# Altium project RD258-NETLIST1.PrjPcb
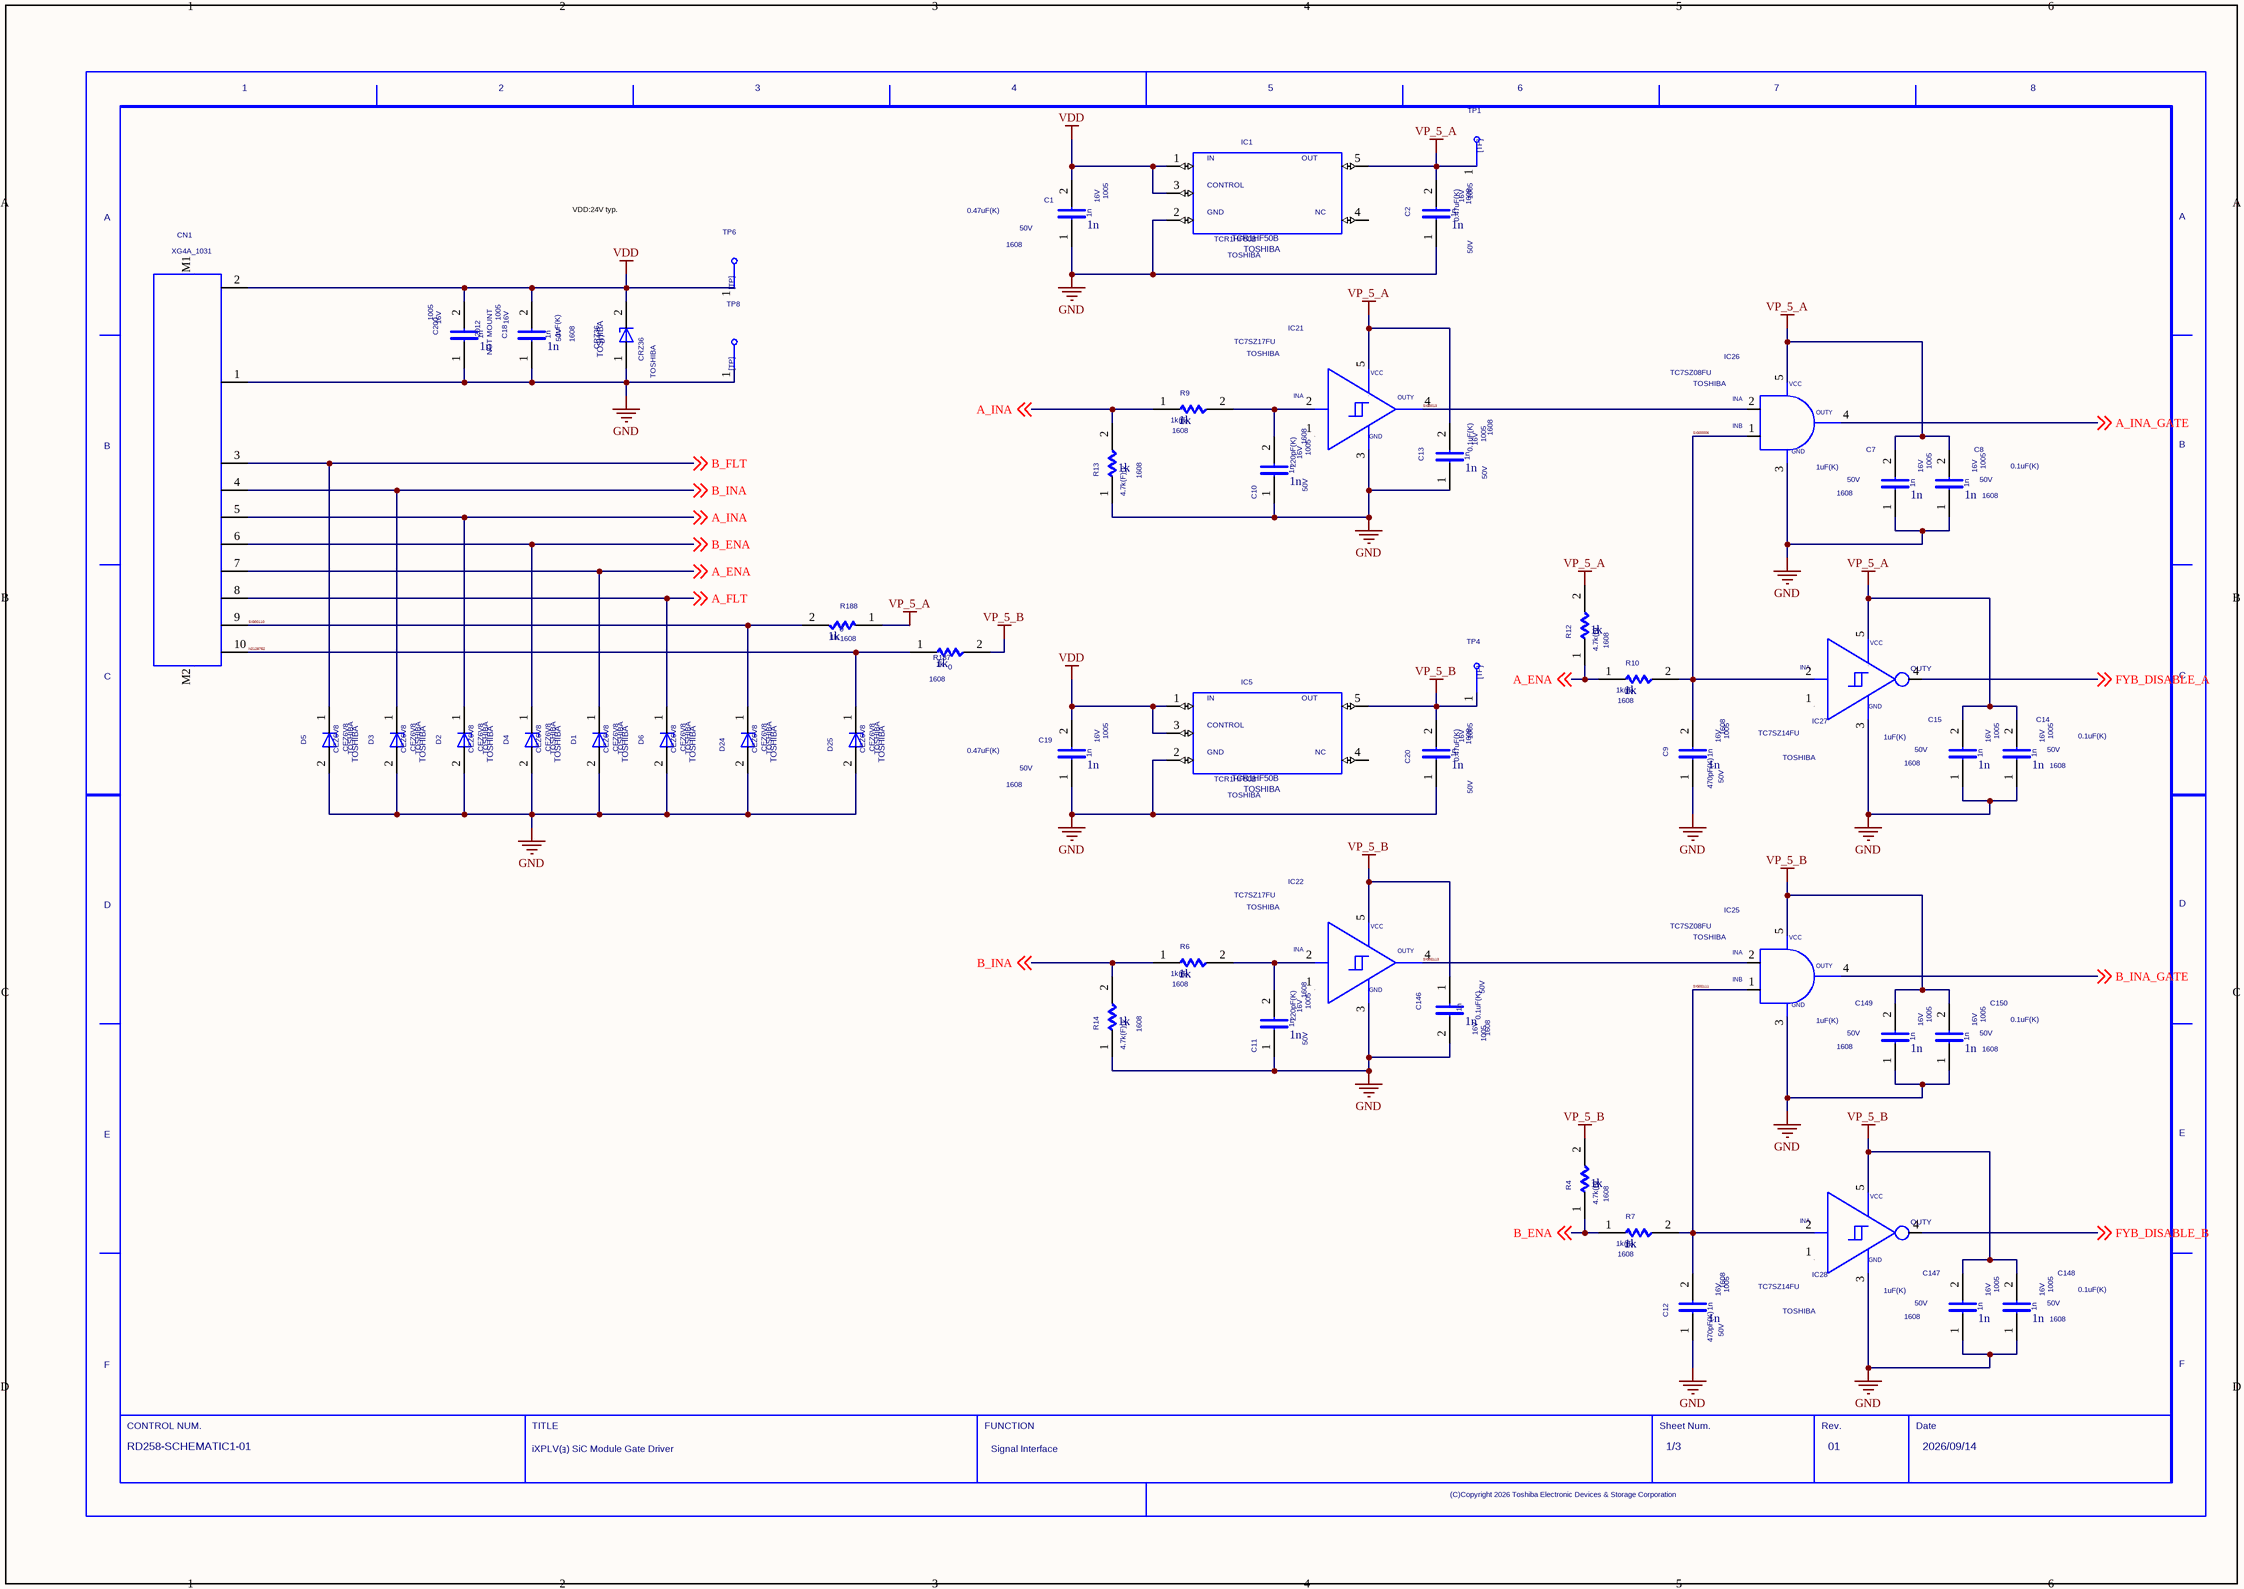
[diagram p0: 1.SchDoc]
3 sheets, 180 parts. Net scope: global (net labels, ports and power ports of the same name join across sheets).
Sheets:
  1.SchDoc
  2.SchDoc
  3.SchDoc

## Sheet 1.SchDoc
size 420 x 297 mm

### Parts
(Parts that share a designator on the sheet are numbered #1, #2 ... from top to bottom, then left to right.)
C1  1n  VAL1: 0.47uF(K)  SIZE: 1005  VOLTAGE: 16V  SIZECODESMD: 1608  VAL2: 50V
C2  1n  VAL1: 0.47uF(K)  SIZE: 1005  VOLTAGE: 16V  SIZECODESMD: 1608  VAL2: 50V
C7  1n  VAL1: 1uF(K)  SIZE: 1005  VOLTAGE: 16V  SIZECODESMD: 1608  VAL2: 50V
C8  1n  VAL1: 0.1uF(K)  SIZE: 1005  VOLTAGE: 16V  SIZECODESMD: 1608  VAL2: 50V
C9  1n  VAL1: 470pF(K)  SIZE: 1005  VOLTAGE: 16V  SIZECODESMD: 1608  VAL2: 50V
C10  1n  VAL1: 220pF(K)  SIZE: 1005  VOLTAGE: 16V  SIZECODESMD: 1608  VAL2: 50V
C11  1n  VAL1: 220pF(K)  SIZE: 1005  VOLTAGE: 16V  SIZECODESMD: 1608  VAL2: 50V
C12  1n  VAL1: 470pF(K)  SIZE: 1005  VOLTAGE: 16V  SIZECODESMD: 1608  VAL2: 50V
C13  1n  VAL1: 0.1uF(K)  SIZE: 1005  VOLTAGE: 16V  SIZECODESMD: 1608  VAL2: 50V
C14  1n  VAL1: 0.1uF(K)  SIZE: 1005  VOLTAGE: 16V  SIZECODESMD: 1608  VAL2: 50V
C15  1n  VAL1: 1uF(K)  SIZE: 1005  VOLTAGE: 16V  SIZECODESMD: 1608  VAL2: 50V
C18  1n  VAL1: 1uF(K)  SIZE: 1005  VOLTAGE: 16V  SIZECODESMD: 1608  VAL2: 50V
C19  1n  VAL1: 0.47uF(K)  SIZE: 1005  VOLTAGE: 16V  SIZECODESMD: 1608  VAL2: 50V
C20  1n  VAL1: 0.47uF(K)  SIZE: 1005  VOLTAGE: 16V  SIZECODESMD: 1608  VAL2: 50V
C146  1n  VAL1: 0.1uF(K)  SIZE: 1005  VOLTAGE: 16V  SIZECODESMD: 1608  VAL2: 50V
C147  1n  VAL1: 1uF(K)  SIZE: 1005  VOLTAGE: 16V  SIZECODESMD: 1608  VAL2: 50V
C148  1n  VAL1: 0.1uF(K)  SIZE: 1005  VOLTAGE: 16V  SIZECODESMD: 1608  VAL2: 50V
C149  1n  VAL1: 1uF(K)  SIZE: 1005  VOLTAGE: 16V  SIZECODESMD: 1608  VAL2: 50V
C150  1n  VAL1: 0.1uF(K)  SIZE: 1005  VOLTAGE: 16V  SIZECODESMD: 1608  VAL2: 50V
C200  1n  SIZE: 1005  VOLTAGE: 16V  SIZECODESMD: 2012  NOTMOUNT: NOT MOUNT
CN1  XG4A_1031
D1  CEZ6V8  VENDOR: TOSHIBA
D2  CEZ6V8  VENDOR: TOSHIBA
D3  CEZ6V8  VENDOR: TOSHIBA
D4  CEZ6V8  VENDOR: TOSHIBA
D5  CEZ6V8  VENDOR: TOSHIBA
D6  CEZ6V8  VENDOR: TOSHIBA
D7  CRZ36  VENDOR: TOSHIBA
D24  CEZ6V8  VENDOR: TOSHIBA
D25  CEZ6V8  VENDOR: TOSHIBA
IC1  TCR1HF50B  VENDOR: TOSHIBA
IC5  TCR1HF50B  VENDOR: TOSHIBA
IC21  USERCOMPTEXT3: TOSHIBA  (hidden comment: TC7PZ17FU)
IC22  USERCOMPTEXT3: TOSHIBA  (hidden comment: TC7PZ17FU)
IC25  USERCOMPTEXT3: TOSHIBA  (hidden comment: TC7WZ08FK)
IC26  USERCOMPTEXT3: TOSHIBA  (hidden comment: TC7WZ08FK)
IC27  USERCOMPTEXT3: TOSHIBA  (hidden comment: TC7PZ17FU)
IC28  USERCOMPTEXT3: TOSHIBA  (hidden comment: TC7PZ17FU)
R4  1k  VAL1: 4.7k(F)  SIZECODESMD: 1608
R6  1k  VAL1: 1k(F)  SIZECODESMD: 1608
R7  1k  VAL1: 1k(F)  SIZECODESMD: 1608
R9  1k  VAL1: 1k(F)  SIZECODESMD: 1608
R10  1k  VAL1: 1k(F)  SIZECODESMD: 1608
R12  1k  VAL1: 4.7k(F)  SIZECODESMD: 1608
R13  1k  VAL1: 4.7k(F)  SIZECODESMD: 1608
R14  1k  VAL1: 4.7k(F)  SIZECODESMD: 1608
R187  1k  VAL1: 0  SIZECODESMD: 1608
R188  1k  VAL1: 0  SIZECODESMD: 1608
TP1  TP  (value not drawn)
TP4  TP  (value not drawn)
TP6  TP  (value not drawn)
TP8  TP  (value not drawn)
U?#1  DATE: 2026/09/14  DRAWINGNUMBER: RD258-SCHEMATIC1-01  TITLE: iXPLV(ｮ) SiC Module Gate Driver  FUNCTION: Signal Interface  SHEETNUMBER: 1/3  REVISION: 01  (hidden comment: WAKU_DEF100)

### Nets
GND: C1.1 C2.1 C7.1 C8.1 C9.1 C10.1 C11.1 C12.1 C13.1 C14.1 C15.1 C18.1 C19.1 C20.1 C146.2 C147.1 C148.1 C149.1 C150.1 C200.1 CN1.1 D1.2(A) D2.2(A) D3.2(A) D4.2(A) D5.2(A) D6.2(A) D7.1(A) D24.2(A) D25.2(A) IC1.2 IC5.2 IC21.3 IC22.3 IC25.3 IC26.3 IC27.3 IC28.3 R13.1 R14.1 TP8.1
VDD: C1.2 C18.2 C19.2 C200.2 CN1.2 D7.2(C) IC1.1 IC1.3 IC5.1 IC5.3 TP6.1
VP_5_A: C2.2 C7.2 C8.2 C13.2 C14.2 C15.2 IC1.5 IC21.5 IC26.5 IC27.5 R12.2 R188.1 TP1.1
VP_5_B: C20.2 C146.1 C147.2 C148.2 C149.2 C150.2 IC5.5 IC22.5 IC25.5 IC28.5 R4.2 R187.2 TP4.1
A_ENA: CN1.7 D1.1(C) R10.1 R12.1 ; off-sheet A_ENA
A_FLT: CN1.8 D6.1(C) ; off-sheet A_FLT
A_INA: CN1.5 D2.1(C) R9.1 R13.2 ; off-sheet A_INA
A_INA_GATE: IC26.4 ; off-sheet A_INA_GATE
B_ENA: CN1.6 D4.1(C) R4.1 R7.1 ; off-sheet B_ENA
B_FLT: CN1.3 D5.1(C) ; off-sheet B_FLT
B_INA: CN1.4 D3.1(C) R6.1 R14.2 ; off-sheet B_INA
B_INA_GATE: IC25.4 ; off-sheet B_INA_GATE
FYB_DISABLE_A: IC27.4 ; off-sheet FYB_DISABLE_A
FYB_DISABLE_B: IC28.4 ; off-sheet FYB_DISABLE_B
N2128752: CN1.10 D25.1(C) R187.1
SIG00006: C9.2 IC26.1 IC27.2 R10.2
SIG0013: IC21.4 IC26.2
SIG00110: CN1.9 D24.1(C) R188.2
SIG00111: C12.2 IC25.1 IC28.2 R7.2
SIG00112: C11.2 IC22.2 R6.2
SIG00113: IC22.4 IC25.2
SIG00237: C10.2 IC21.2 R9.2

Not connected (* = marked no-connect by the designer): CN1 M1 M2; IC1 4; IC5 4; IC21 1; IC22 1; IC27 1; IC28 1

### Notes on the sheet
- VDD:24V typ.

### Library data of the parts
C1 C19 = C: TIME: 11:55:01; UPDATEUSER: HP_Z8_KEYSHOT; SAVECOUNT: 2; TC1: 0; PSPICETEMPLATE: C^@REFDES %1 %2 ?TOLERANCE¦C^@REFDES¦ @VALUE ?IC/IC=@IC/ TC=@TC1,@TC2 ?TOLERANCE¦\n.model C^@REFDES CAP C=1 DEV=@TOLERANCE% TC1=@TC1 TC2=@TC2 VC1=@VC1 VC2=@VC2¦; ORIGINALSYMBOLORIGIN: (0,0); INSTANCENAME: INS1386363
C2 C20 = C: TIME: 11:55:01; UPDATEUSER: HP_Z8_KEYSHOT; SAVECOUNT: 2; TC1: 0; PSPICETEMPLATE: C^@REFDES %1 %2 ?TOLERANCE¦C^@REFDES¦ @VALUE ?IC/IC=@IC/ TC=@TC1,@TC2 ?TOLERANCE¦\n.model C^@REFDES CAP C=1 DEV=@TOLERANCE% TC1=@TC1 TC2=@TC2 VC1=@VC1 VC2=@VC2¦; ORIGINALSYMBOLORIGIN: (0,0); INSTANCENAME: INS1386331
C7 C15 C147 C149 = C: TIME: 11:55:01; UPDATEUSER: HP_Z8_KEYSHOT; SAVECOUNT: 2; TC1: 0; PSPICETEMPLATE: C^@REFDES %1 %2 ?TOLERANCE¦C^@REFDES¦ @VALUE ?IC/IC=@IC/ TC=@TC1,@TC2 ?TOLERANCE¦\n.model C^@REFDES CAP C=1 DEV=@TOLERANCE% TC1=@TC1 TC2=@TC2 VC1=@VC1 VC2=@VC2¦; ORIGINALSYMBOLORIGIN: (0,0); INSTANCENAME: INS1386091
C8 C13 C14 C146 C148 C150 = C: TIME: 11:55:01; UPDATEUSER: HP_Z8_KEYSHOT; SAVECOUNT: 2; TC1: 0; PSPICETEMPLATE: C^@REFDES %1 %2 ?TOLERANCE¦C^@REFDES¦ @VALUE ?IC/IC=@IC/ TC=@TC1,@TC2 ?TOLERANCE¦\n.model C^@REFDES CAP C=1 DEV=@TOLERANCE% TC1=@TC1 TC2=@TC2 VC1=@VC1 VC2=@VC2¦; ORIGINALSYMBOLORIGIN: (0,0); INSTANCENAME: INS1386793
C9 C12 = C: TIME: 11:55:01; UPDATEUSER: HP_Z8_KEYSHOT; SAVECOUNT: 2; TC1: 0; PSPICETEMPLATE: C^@REFDES %1 %2 ?TOLERANCE¦C^@REFDES¦ @VALUE ?IC/IC=@IC/ TC=@TC1,@TC2 ?TOLERANCE¦\n.model C^@REFDES CAP C=1 DEV=@TOLERANCE% TC1=@TC1 TC2=@TC2 VC1=@VC1 VC2=@VC2¦; ORIGINALSYMBOLORIGIN: (0,0); INSTANCENAME: INS1386155
C10 C11 = C: TIME: 11:55:01; UPDATEUSER: HP_Z8_KEYSHOT; SAVECOUNT: 2; TC1: 0; PSPICETEMPLATE: C^@REFDES %1 %2 ?TOLERANCE¦C^@REFDES¦ @VALUE ?IC/IC=@IC/ TC=@TC1,@TC2 ?TOLERANCE¦\n.model C^@REFDES CAP C=1 DEV=@TOLERANCE% TC1=@TC1 TC2=@TC2 VC1=@VC1 VC2=@VC2¦; ORIGINALSYMBOLORIGIN: (0,0); INSTANCENAME: INS1386019
C18 = C: TIME: 11:55:01; UPDATEUSER: HP_Z8_KEYSHOT; SAVECOUNT: 2; TC1: 0; PSPICETEMPLATE: C^@REFDES %1 %2 ?TOLERANCE¦C^@REFDES¦ @VALUE ?IC/IC=@IC/ TC=@TC1,@TC2 ?TOLERANCE¦\n.model C^@REFDES CAP C=1 DEV=@TOLERANCE% TC1=@TC1 TC2=@TC2 VC1=@VC1 VC2=@VC2¦; ORIGINALSYMBOLORIGIN: (0,0); INSTANCENAME: INS1386685
C200 = C: TIME: 11:55:01; UPDATEUSER: HP_Z8_KEYSHOT; SAVECOUNT: 2; TC1: 0; PSPICETEMPLATE: C^@REFDES %1 %2 ?TOLERANCE¦C^@REFDES¦ @VALUE ?IC/IC=@IC/ TC=@TC1,@TC2 ?TOLERANCE¦\n.model C^@REFDES CAP C=1 DEV=@TOLERANCE% TC1=@TC1 TC2=@TC2 VC1=@VC1 VC2=@VC2¦; ORIGINALSYMBOLORIGIN: (0,0); INSTANCENAME: INS2126613
CN1 = XG4A_1031_1: PART NUMBER: XG4A-1031; TIME: 11:54:59; UPDATEUSER: t5459927; UPDATETIME: 17:44:51; SAVECOUNT: 12; PSPICETEMPLATE: X^@REFDES %1 %2 %3 %4 %5 %6 %7 %8 %9 %10 %M1 %M2 @MODEL; OriginalSymbolOrigin: (0,73660)
D1-D6 D24 D25 = CEZ6V8: TIME: 14:49:55; UPDATEUSER: fukuda-y; UPDATETIME: 08:18:42; SAVECOUNT: 6; SAVEAREA0: -4630,-153,17114,13055; PSPICETEMPLATE: X^@REFDES %A %C @MODEL; ORIGINALSYMBOLORIGIN: (0,0); INSTANCENAME: INS1385789
D7 = CRZ36: TIME: 14:49:55; UPDATEUSER: fukuda-y; UPDATETIME: 08:18:42; SAVECOUNT: 6; SAVEAREA0: -4630,-153,17114,13055; PSPICETEMPLATE: X^@REFDES %A %C @MODEL; ORIGINALSYMBOLORIGIN: (0,0); INSTANCENAME: INS1385571
IC1 IC5 = TCR1HF50B: TIME: 11:54:59; UPDATEUSER: t5459927; UPDATETIME: 10:27:35; SAVECOUNT: 4; PSPICETEMPLATE: X^@REFDES %IN %GND %CONTROL %NC %OUT @MODEL; OriginalSymbolOrigin: (-2540,0); INSTANCENAME: INS1386243
IC21 IC22 = TC7SZ17FU: TIME: 11:55:01; UPDATEUSER: t5459927; UPDATETIME: 17:52:26; SAVECOUNT: 10; SPLIT_INST: TRUE; PSPICETEMPLATE: X^@REFDES %1A %GND %2A %2Y %VCC %1Y @MODEL; SWAP_INFO: (S1+S2); OriginalSymbolOrigin: (0,15240)
IC25 IC26 = TC7SZ08FU: TIME: 08:52:39; UPDATEUSER: sptcae09; UPDATETIME: 16:09:46; SAVECOUNT: 9; SWAP_INFO: (S1+S2); ORDER: $pOrder; SPLIT_INST: TRUE; ・: 20mA; USER_VALUE: TC7W00FK; PSPICETEMPLATE: X^@REFDES %1A %1B %2Y %GND %2A %2B %1Y %VCC @MODEL; DESCRIPTION-A: NAND 2ch Logic; ORIGINALSYMBOLORIGIN: (2540,0)
IC27 IC28 = TC7SZ14FU: TIME: 11:55:01; UPDATEUSER: t5459927; UPDATETIME: 09:40:09; SAVECOUNT: 11; SPLIT_INST: TRUE; PSPICETEMPLATE: X^@REFDES %1A %GND %2A %2Y %VCC %1Y @MODEL; SWAP_INFO: (S1+S2); OriginalSymbolOrigin: (0,15240)
R4 R6 R7 R9 R10 R12 = R_Dup1: TIME: 11:54:58; UPDATEUSER: HP_Z8_KEYSHOT; UPDATETIME: 11:54:59; SAVECOUNT: 2; WATT: 0.125; COMP: R; TC1: 0; PSPICETEMPLATE: R^@REFDES %1 %2 ?TOLERANCE¦R^@REFDES¦ @VALUE TC=@TC1,@TC2 ?TOLERANCE¦\n.model R^@REFDES RES R=1 DEV=@TOLERANCE% TC1=@TC1 TC2=@TC2¦; ORIGINALSYMBOLORIGIN: (0,0); VAL2: 100mW; INSTANCENAME: INS1387005
R13 R14 = R_Dup1: TIME: 11:54:58; UPDATEUSER: HP_Z8_KEYSHOT; UPDATETIME: 11:54:59; SAVECOUNT: 2; WATT: 0.125; COMP: R; TC1: 0; PSPICETEMPLATE: R^@REFDES %1 %2 ?TOLERANCE¦R^@REFDES¦ @VALUE TC=@TC1,@TC2 ?TOLERANCE¦\n.model R^@REFDES RES R=1 DEV=@TOLERANCE% TC1=@TC1 TC2=@TC2¦; ORIGINALSYMBOLORIGIN: (0,0); VAL2: 100mW; INSTANCENAME: INS2060849
R187 = R_Dup1: TIME: 11:54:58; UPDATEUSER: HP_Z8_KEYSHOT; UPDATETIME: 11:54:59; SAVECOUNT: 2; WATT: 0.125; COMP: R; PSPICETEMPLATE: R^@REFDES %1 %2 ?TOLERANCE¦R^@REFDES¦ @VALUE TC=@TC1,@TC2 ?TOLERANCE¦\n.model R^@REFDES RES R=1 DEV=@TOLERANCE% TC1=@TC1 TC2=@TC2¦; ORIGINALSYMBOLORIGIN: (0,0); INSTANCENAME: INS2126667
R188 = R_Dup1: TIME: 11:54:58; UPDATEUSER: HP_Z8_KEYSHOT; UPDATETIME: 11:54:59; SAVECOUNT: 2; WATT: 0.125; COMP: R; PSPICETEMPLATE: R^@REFDES %1 %2 ?TOLERANCE¦R^@REFDES¦ @VALUE TC=@TC1,@TC2 ?TOLERANCE¦\n.model R^@REFDES RES R=1 DEV=@TOLERANCE% TC1=@TC1 TC2=@TC2¦; ORIGINALSYMBOLORIGIN: (0,0); INSTANCENAME: INS2126643
TP1 = TP: TIME: 16:12:21; UPDATEUSER: fukuda-y; UPDATETIME: 16:18:11; SAVECOUNT: 2; SAVEAREA0: -242,-92,12810,7836; ORIGINALSYMBOLORIGIN: (0,0); INSTANCENAME: INS1385435
TP4 = TP: TIME: 16:12:21; UPDATEUSER: fukuda-y; UPDATETIME: 16:18:11; SAVECOUNT: 2; SAVEAREA0: -242,-92,12810,7836; ORIGINALSYMBOLORIGIN: (0,0); INSTANCENAME: INS2191044
TP6 = TP: TIME: 16:12:21; UPDATEUSER: fukuda-y; UPDATETIME: 16:18:11; SAVECOUNT: 2; SAVEAREA0: -242,-92,12810,7836; ORIGINALSYMBOLORIGIN: (0,0); INSTANCENAME: INS1386079
TP8 = TP: TIME: 16:12:21; UPDATEUSER: fukuda-y; UPDATETIME: 16:18:11; SAVECOUNT: 2; SAVEAREA0: -242,-92,12810,7836; ORIGINALSYMBOLORIGIN: (0,0); INSTANCENAME: INS1386853
U?#1 = WAKU_DEF100: PLOTTIME: HH:MM; SAVEAREA0: -63393,-16950,474261,314592; TIME: 14:30:25; UPDATEUSER: d5009410; UPDATETIME: 15:37:05; SAVECOUNT: 4; OriginalSymbolOrigin: (10160,284480); SHTSAVECOUNT: 60; NUMBER DEVICES IN PACKAGE: 1; SHEET NUM: X/X; PIN NUMBERS VISIBLE: False; CONTROL NUM: RD256-SCHEMATIC-0; PIN NAMES ROTATE: True

## Sheet 2.SchDoc
size 420 x 297 mm
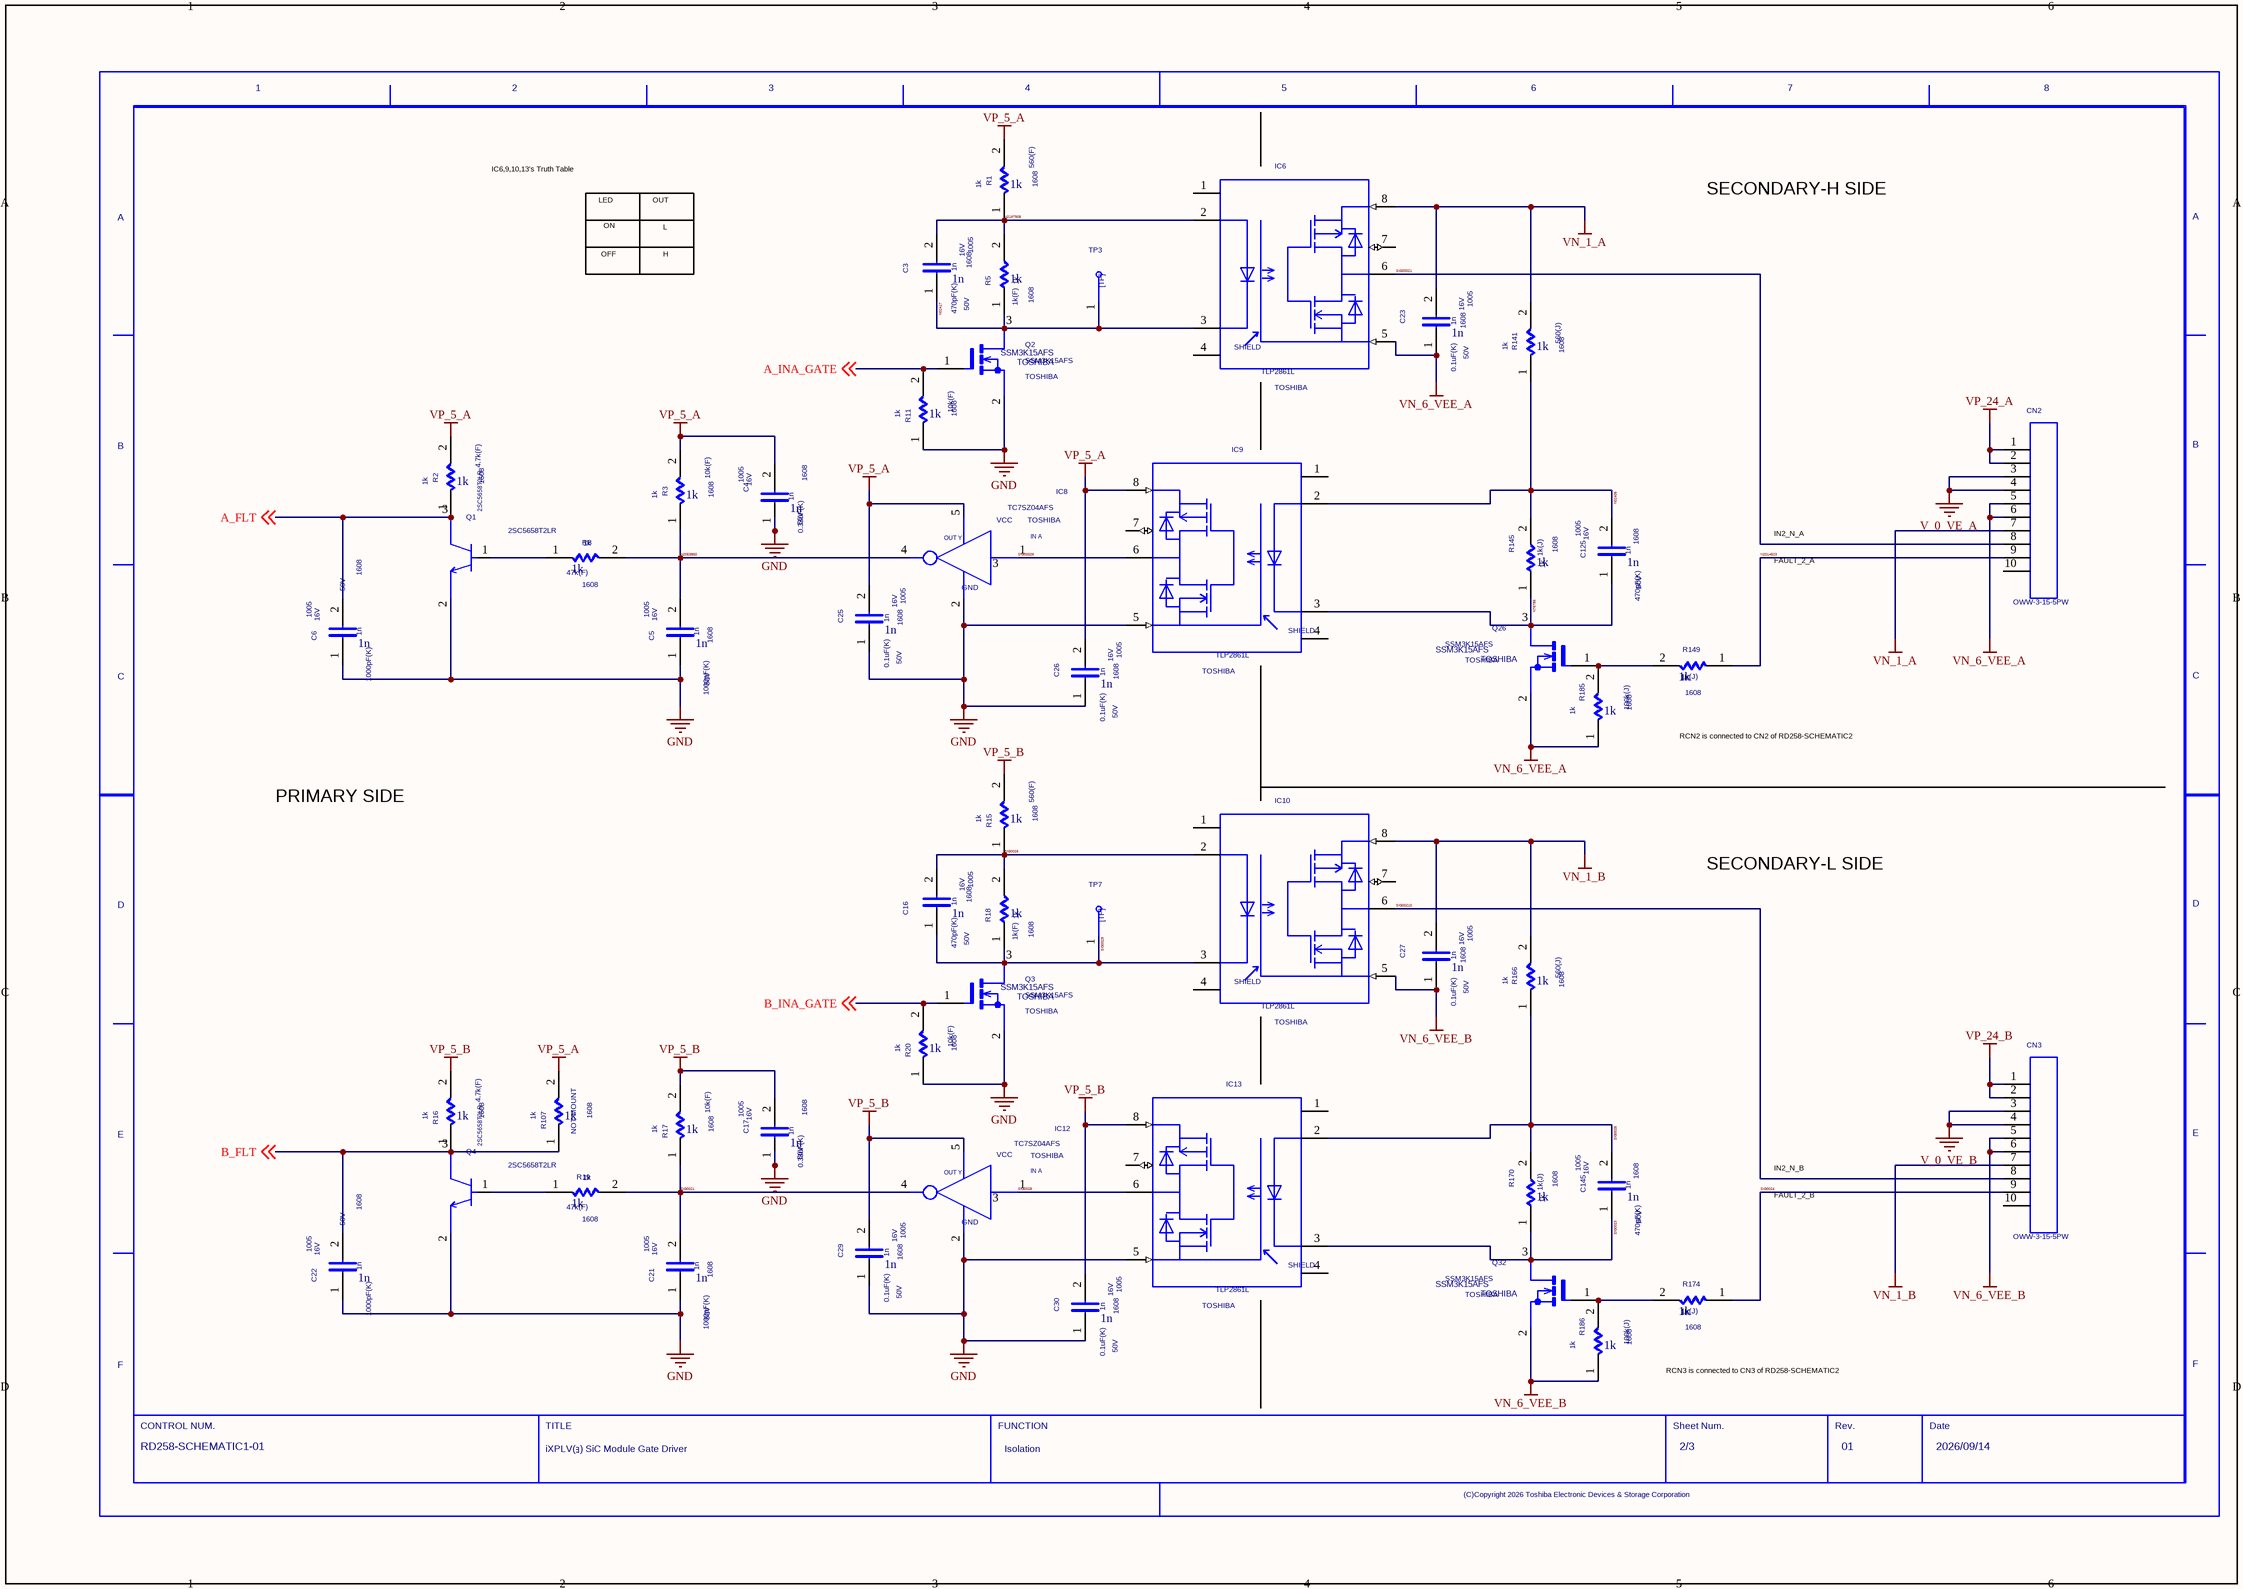
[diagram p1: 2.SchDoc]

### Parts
(Parts that share a designator on the sheet are numbered #1, #2 ... from top to bottom, then left to right.)
C3  1n  VAL1: 470pF(K)  SIZE: 1005  VOLTAGE: 16V  SIZECODESMD: 1608  VAL2: 50V
C4  1n  VAL1: 0.33uF(K)  SIZE: 1005  VOLTAGE: 16V  SIZECODESMD: 1608  VAL2: 50V
C5  1n  VAL1: 1000pF(K)  SIZE: 1005  VOLTAGE: 16V  SIZECODESMD: 1608  VAL2: 50V
C6  1n  VAL1: 1000pF(K)  SIZE: 1005  VOLTAGE: 16V  SIZECODESMD: 1608  VAL2: 50V
C16  1n  VAL1: 470pF(K)  SIZE: 1005  VOLTAGE: 16V  SIZECODESMD: 1608  VAL2: 50V
C17  1n  VAL1: 0.33uF(K)  SIZE: 1005  VOLTAGE: 16V  SIZECODESMD: 1608  VAL2: 50V
C21  1n  VAL1: 1000pF(K)  SIZE: 1005  VOLTAGE: 16V  SIZECODESMD: 1608  VAL2: 50V
C22  1n  VAL1: 1000pF(K)  SIZE: 1005  VOLTAGE: 16V  SIZECODESMD: 1608  VAL2: 50V
C23  1n  VAL1: 0.1uF(K)  SIZE: 1005  VOLTAGE: 16V  SIZECODESMD: 1608  VAL2: 50V
C25  1n  VAL1: 0.1uF(K)  SIZE: 1005  VOLTAGE: 16V  SIZECODESMD: 1608  VAL2: 50V
C26  1n  VAL1: 0.1uF(K)  SIZE: 1005  VOLTAGE: 16V  SIZECODESMD: 1608  VAL2: 50V
C27  1n  VAL1: 0.1uF(K)  SIZE: 1005  VOLTAGE: 16V  SIZECODESMD: 1608  VAL2: 50V
C29  1n  VAL1: 0.1uF(K)  SIZE: 1005  VOLTAGE: 16V  SIZECODESMD: 1608  VAL2: 50V
C30  1n  VAL1: 0.1uF(K)  SIZE: 1005  VOLTAGE: 16V  SIZECODESMD: 1608  VAL2: 50V
C125  1n  VAL1: 470pF(K)  SIZE: 1005  VOLTAGE: 16V  SIZECODESMD: 1608  VAL2: 50V
C145  1n  VAL1: 470pF(K)  SIZE: 1005  VOLTAGE: 16V  SIZECODESMD: 1608  VAL2: 50V
CN2  VAL3: OWW-3-15-5PW  (hidden comment: CN9_2)
CN3  VAL3: OWW-3-15-5PW  (hidden comment: CN9_2)
IC6  USERCOMPTEXT3: TOSHIBA  (hidden comment: TLP2861L)
IC8  USERCOMPTEXT3: TOSHIBA  (hidden comment: TC7SZ04AFS)
IC9  USERCOMPTEXT3: TOSHIBA  (hidden comment: TLP2861L)
IC10  USERCOMPTEXT3: TOSHIBA  (hidden comment: TLP2861L)
IC12  USERCOMPTEXT3: TOSHIBA  (hidden comment: TC7SZ04AFS)
IC13  USERCOMPTEXT3: TOSHIBA  (hidden comment: TLP2861L)
Q1  2SC5658T2LR
Q2  SSM3K15AFS  VENDOR: TOSHIBA
Q3  SSM3K15AFS  VENDOR: TOSHIBA
Q4  2SC5658T2LR
Q26  SSM3K15AFS  VENDOR: TOSHIBA
Q32  SSM3K15AFS  VENDOR: TOSHIBA
R1  1k  VAL1: 560(F)  SIZECODESMD: 1608
R2  1k  VAL1: 4.7k(F)  SIZECODESMD: 1608
R3  1k  VAL1: 10k(F)  SIZECODESMD: 1608
R5  1k  VAL1: 1k(F)  SIZECODESMD: 1608
R8  1k  VAL1: 47k(F)  SIZECODESMD: 1608
R11  1k  VAL1: 10k(F)  SIZECODESMD: 1608
R15  1k  VAL1: 560(F)  SIZECODESMD: 1608
R16  1k  VAL1: 4.7k(F)  SIZECODESMD: 1608
R17  1k  VAL1: 10k(F)  SIZECODESMD: 1608
R18  1k  VAL1: 1k(F)  SIZECODESMD: 1608
R19  1k  VAL1: 47k(F)  SIZECODESMD: 1608
R20  1k  VAL1: 10k(F)  SIZECODESMD: 1608
R107  1k  NOTMOUNT: NOT MOUNT  SIZECODESMD: 1608
R141  1k  VAL1: 560(J)  SIZECODESMD: 1608
R145  1k  VAL1: 1k(J)  SIZECODESMD: 1608
R149  1k  VAL1: 1k(J)  SIZECODESMD: 1608
R166  1k  VAL1: 560(J)  SIZECODESMD: 1608
R170  1k  VAL1: 1k(J)  SIZECODESMD: 1608
R174  1k  VAL1: 1k(J)  SIZECODESMD: 1608
R185  1k  VAL1: 100k(J)  SIZECODESMD: 1608
R186  1k  VAL1: 100k(J)  SIZECODESMD: 1608
TP3  TP  (value not drawn)
TP7  TP  (value not drawn)
U?#2  DATE: 2026/09/14  DRAWINGNUMBER: RD258-SCHEMATIC1-01  TITLE: iXPLV(ｮ) SiC Module Gate Driver  FUNCTION: Isolation  SHEETNUMBER: 2/3  REVISION: 01  (hidden comment: WAKU_DEF100)

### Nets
GND: C4.1 C5.1 C6.1 C17.1 C21.1 C22.1 C25.1 C26.1 C29.1 C30.1 IC8.2 IC9.5 IC12.2 IC13.5 Q1.2(E) Q2.2(S) Q3.2(S) Q4.2(E) R11.1 R20.1
V_0_VE_A: CN2.3 CN2.4
V_0_VE_B: CN3.3 CN3.4
VN_1_A: C23.2 CN2.7 IC6.8 R141.2
VN_1_B: C27.2 CN3.7 IC10.8 R166.2
VN_6_VEE_A: C23.1 CN2.5 CN2.6 IC6.5 Q26.2(S) R185.1
VN_6_VEE_B: C27.1 CN3.5 CN3.6 IC10.5 Q32.2(S) R186.1
VP_5_A: C4.2 C25.2 C26.2 IC8.5 IC9.8 R1.2 R2.2 R3.2 R107.2
VP_5_B: C17.2 C29.2 C30.2 IC12.5 IC13.8 R15.2 R16.2 R17.2
VP_24_A: CN2.1 CN2.2
VP_24_B: CN3.1 CN3.2
A_FLT: C6.2 Q1.3(C) R2.1 ; off-sheet A_FLT
A_INA_GATE: Q2.1(G) R11.2 ; off-sheet A_INA_GATE
B_FLT: C22.2 Q4.3(C) R16.1 R107.1 ; off-sheet B_FLT
B_INA_GATE: Q3.1(G) R20.2 ; off-sheet B_INA_GATE
N02405: C125.2 IC9.2 R141.1 R145.2
N02417: C3.1 IC6.3 Q2.3(D) R5.1 TP3.1
N76786: C125.1 IC9.3 Q26.3(D) R145.1
N2014523: CN2.9 R149.1
N2053860: C5.2 IC8.4 R3.1 R8.2
N2197908: C3.2 IC6.2 R1.1 R5.2
SIG00005: Q1.1(B) R8.1
SIG0021: C21.2 IC12.4 R17.1 R19.2
SIG00021: CN2.8 IC6.6
SIG0022: Q32.1(G) R174.2 R186.2
SIG0023: C145.1 IC13.3 Q32.3(D) R170.1
SIG0024: CN3.9 R174.1
SIG0025: C145.2 IC13.2 R166.1 R170.2
SIG00026: IC8.1 IC9.6
SIG0026: C16.2 IC10.2 R15.1 R18.2
SIG0027: Q4.1(B) R19.1
SIG0028: IC12.1 IC13.6
SIG0029: C16.1 IC10.3 Q3.3(D) R18.1 TP7.1
SIG00190: Q26.1(G) R149.2 R185.2
SIG00210: CN3.8 IC10.6

Not connected (* = marked no-connect by the designer): CN2 10; CN3 10; IC6 1 4 7; IC8 3; IC9 1 4 7; IC10 1 4 7; IC12 3; IC13 1 4 7

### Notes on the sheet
- IC6,9,10,13's Truth Table
- LED
- OFF
- ON
- OUT
- H
- L
- SECONDARY-H SIDE
- IN2_N_A
- FAULT_2_A
- PRIMARY SIDE
- RCN2 is connected to CN2 of RD258-SCHEMATIC2
- SECONDARY-L SIDE
- FAULT_2_B
- IN2_N_B
- RCN3 is connected to CN3 of RD258-SCHEMATIC2

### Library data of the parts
C3 C16 = C: TIME: 11:55:01; UPDATEUSER: HP_Z8_KEYSHOT; SAVECOUNT: 2; TC1: 0; PSPICETEMPLATE: C^@REFDES %1 %2 ?TOLERANCE¦C^@REFDES¦ @VALUE ?IC/IC=@IC/ TC=@TC1,@TC2 ?TOLERANCE¦\n.model C^@REFDES CAP C=1 DEV=@TOLERANCE% TC1=@TC1 TC2=@TC2 VC1=@VC1 VC2=@VC2¦; ORIGINALSYMBOLORIGIN: (0,0); INSTANCENAME: INS2054894
C4 C17 = C: TIME: 11:55:01; UPDATEUSER: HP_Z8_KEYSHOT; SAVECOUNT: 2; TC1: 0; PSPICETEMPLATE: C^@REFDES %1 %2 ?TOLERANCE¦C^@REFDES¦ @VALUE ?IC/IC=@IC/ TC=@TC1,@TC2 ?TOLERANCE¦\n.model C^@REFDES CAP C=1 DEV=@TOLERANCE% TC1=@TC1 TC2=@TC2 VC1=@VC1 VC2=@VC2¦; ORIGINALSYMBOLORIGIN: (0,0); INSTANCENAME: INS2053830
C5 C6 C21 C22 = C: TIME: 11:55:01; UPDATEUSER: HP_Z8_KEYSHOT; SAVECOUNT: 2; TC1: 0; PSPICETEMPLATE: C^@REFDES %1 %2 ?TOLERANCE¦C^@REFDES¦ @VALUE ?IC/IC=@IC/ TC=@TC1,@TC2 ?TOLERANCE¦\n.model C^@REFDES CAP C=1 DEV=@TOLERANCE% TC1=@TC1 TC2=@TC2 VC1=@VC1 VC2=@VC2¦; ORIGINALSYMBOLORIGIN: (0,0); INSTANCENAME: INS2053916
C23 C27 = C: TIME: 11:55:01; UPDATEUSER: HP_Z8_KEYSHOT; SAVECOUNT: 2; TC1: 0; PSPICETEMPLATE: C^@REFDES %1 %2 ?TOLERANCE¦C^@REFDES¦ @VALUE ?IC/IC=@IC/ TC=@TC1,@TC2 ?TOLERANCE¦\n.model C^@REFDES CAP C=1 DEV=@TOLERANCE% TC1=@TC1 TC2=@TC2 VC1=@VC1 VC2=@VC2¦; ORIGINALSYMBOLORIGIN: (0,0); INSTANCENAME: INS1388174
C25 C26 C29 C30 = C: TIME: 11:55:01; UPDATEUSER: HP_Z8_KEYSHOT; SAVECOUNT: 2; TC1: 0; PSPICETEMPLATE: C^@REFDES %1 %2 ?TOLERANCE¦C^@REFDES¦ @VALUE ?IC/IC=@IC/ TC=@TC1,@TC2 ?TOLERANCE¦\n.model C^@REFDES CAP C=1 DEV=@TOLERANCE% TC1=@TC1 TC2=@TC2 VC1=@VC1 VC2=@VC2¦; ORIGINALSYMBOLORIGIN: (0,0); INSTANCENAME: INS1387946
C125 C145 = C: TIME: 11:55:01; UPDATEUSER: HP_Z8_KEYSHOT; SAVECOUNT: 2; TC1: 0; PSPICETEMPLATE: C^@REFDES %1 %2 ?TOLERANCE¦C^@REFDES¦ @VALUE ?IC/IC=@IC/ TC=@TC1,@TC2 ?TOLERANCE¦\n.model C^@REFDES CAP C=1 DEV=@TOLERANCE% TC1=@TC1 TC2=@TC2 VC1=@VC1 VC2=@VC2¦; ORIGINALSYMBOLORIGIN: (0,0); INSTANCENAME: INS2013765
CN2 CN3 = CN10_1: TIME: 08:48:13; UPDATEUSER: t5459927; UPDATETIME: 15:38:59; SAVECOUNT: 3; PSPICETEMPLATE: X^@REFDES %1 %2 %3 %4 %5 %6 %7 %8 %9 %10 %M1 %M2 @MODEL; USER_VALUE: XG4A-1031; OriginalSymbolOrigin: (0,0)
IC6 IC9 IC10 IC13 = TLP2861: TIME: 11:54:59; UPDATEUSER: t5459927; UPDATETIME: 10:22:13; SAVECOUNT: 4; PSPICETEMPLATE: X^@REFDES %1 %2 %3 %4 %5 %6 %7 %8 @MODEL; SAVEAREA0: -29717,-10800,67926,51382; OriginalSymbolOrigin: (5080,35560)
IC8 IC12 = TC7SZ04AFS: TIME: 11:55:02; UPDATEUSER: t5459927; UPDATETIME: 19:30:29; SAVECOUNT: 6; PSPICETEMPLATE: X^@REFDES %INA %GND %NC %OUTY %VCC @MODEL; OriginalSymbolOrigin: (0,-5080); INSTANCENAME: INS2077754
Q1 Q4 = 2SC5658J: TIME: 09:39:04; UPDATEUSER: 19910145; UPDATETIME: 15:12:10; SAVECOUNT: 8; VENDOR: ROHM; SAVEAREA0: -6194,-158,18648,15662; PSPICETEMPLATE: X^@REFDES %C %B %E @MODEL; ORIGINALSYMBOLORIGIN: (0,0); INSTANCENAME: INS2053972
Q2 Q3 = SSM3K15AFS: TIME: 11:54:59; UPDATEUSER: HP_Z8_KEYSHOT; UPDATETIME: 11:55:00; SAVECOUNT: 2; ORIGINALSYMBOLORIGIN: (0,0); PSPICETEMPLATE: X^@REFDES %D %G %S @MODEL; INSTANCENAME: INS2055002
Q26 Q32 = SSM3K15AFS: TIME: 11:54:59; UPDATEUSER: HP_Z8_KEYSHOT; UPDATETIME: 11:55:00; SAVECOUNT: 2; ORIGINALSYMBOLORIGIN: (0,0); PSPICETEMPLATE: X^@REFDES %D %G %S @MODEL; INSTANCENAME: INS2013847
R1-R3 R11 R15-R17 R20 = R_Dup1: TIME: 11:54:58; UPDATEUSER: HP_Z8_KEYSHOT; UPDATETIME: 11:54:59; SAVECOUNT: 2; WATT: 0.125; COMP: R; TC1: 0; PSPICETEMPLATE: R^@REFDES %1 %2 ?TOLERANCE¦R^@REFDES¦ @VALUE TC=@TC1,@TC2 ?TOLERANCE¦\n.model R^@REFDES RES R=1 DEV=@TOLERANCE% TC1=@TC1 TC2=@TC2¦; ORIGINALSYMBOLORIGIN: (0,0); VAL2: 100mW; INSTANCENAME: INS2053752
R5 R18 = R_Dup1: TIME: 11:54:58; UPDATEUSER: HP_Z8_KEYSHOT; UPDATETIME: 11:54:59; SAVECOUNT: 2; WATT: 0.125; COMP: R; TC1: 0; PSPICETEMPLATE: R^@REFDES %1 %2 ?TOLERANCE¦R^@REFDES¦ @VALUE TC=@TC1,@TC2 ?TOLERANCE¦\n.model R^@REFDES RES R=1 DEV=@TOLERANCE% TC1=@TC1 TC2=@TC2¦; ORIGINALSYMBOLORIGIN: (0,0); VAL2: 100mW; INSTANCENAME: INS2054922
R8 R19 = R_Dup1: TIME: 11:54:58; UPDATEUSER: HP_Z8_KEYSHOT; UPDATETIME: 11:54:59; SAVECOUNT: 2; WATT: 0.125; COMP: R; TC1: 0; PSPICETEMPLATE: R^@REFDES %1 %2 ?TOLERANCE¦R^@REFDES¦ @VALUE TC=@TC1,@TC2 ?TOLERANCE¦\n.model R^@REFDES RES R=1 DEV=@TOLERANCE% TC1=@TC1 TC2=@TC2¦; ORIGINALSYMBOLORIGIN: (0,0); VAL2: 100mW; INSTANCENAME: INS2053892
R107 = R_Dup1: TIME: 11:54:58; UPDATEUSER: HP_Z8_KEYSHOT; UPDATETIME: 11:54:59; SAVECOUNT: 2; WATT: 0.125; COMP: R; TC1: 0; PSPICETEMPLATE: R^@REFDES %1 %2 ?TOLERANCE¦R^@REFDES¦ @VALUE TC=@TC1,@TC2 ?TOLERANCE¦\n.model R^@REFDES RES R=1 DEV=@TOLERANCE% TC1=@TC1 TC2=@TC2¦; ORIGINALSYMBOLORIGIN: (0,0); INSTANCENAME: INS2053752
R141 R166 = R_Dup1: TIME: 11:54:58; UPDATEUSER: HP_Z8_KEYSHOT; UPDATETIME: 11:54:59; SAVECOUNT: 2; WATT: 0.125; COMP: R; TC1: 0; PSPICETEMPLATE: R^@REFDES %1 %2 ?TOLERANCE¦R^@REFDES¦ @VALUE TC=@TC1,@TC2 ?TOLERANCE¦\n.model R^@REFDES RES R=1 DEV=@TOLERANCE% TC1=@TC1 TC2=@TC2¦; ORIGINALSYMBOLORIGIN: (0,0); VAL2: 100mW; INSTANCENAME: INS2013711
R145 R149 R170 R174 = R_Dup1: TIME: 11:54:58; UPDATEUSER: HP_Z8_KEYSHOT; UPDATETIME: 11:54:59; SAVECOUNT: 2; WATT: 0.125; COMP: R; TC1: 0; PSPICETEMPLATE: R^@REFDES %1 %2 ?TOLERANCE¦R^@REFDES¦ @VALUE TC=@TC1,@TC2 ?TOLERANCE¦\n.model R^@REFDES RES R=1 DEV=@TOLERANCE% TC1=@TC1 TC2=@TC2¦; ORIGINALSYMBOLORIGIN: (0,0); VAL2: 100mW; INSTANCENAME: INS2013869
R185 R186 = R_Dup1: TIME: 11:54:58; UPDATEUSER: HP_Z8_KEYSHOT; UPDATETIME: 11:54:59; SAVECOUNT: 2; WATT: 0.125; COMP: R; TC1: 0; PSPICETEMPLATE: R^@REFDES %1 %2 ?TOLERANCE¦R^@REFDES¦ @VALUE TC=@TC1,@TC2 ?TOLERANCE¦\n.model R^@REFDES RES R=1 DEV=@TOLERANCE% TC1=@TC1 TC2=@TC2¦; ORIGINALSYMBOLORIGIN: (0,0); VAL2: 100mW; INSTANCENAME: INS2014404
TP3 TP7 = TP: TIME: 16:12:21; UPDATEUSER: fukuda-y; UPDATETIME: 16:18:11; SAVECOUNT: 2; SAVEAREA0: -242,-92,12810,7836; ORIGINALSYMBOLORIGIN: (0,0); INSTANCENAME: INS2054950
U?#2 = WAKU_DEF100: PLOTTIME: HH:MM; SAVEAREA0: -63393,-16950,474261,314592; TIME: 14:30:25; UPDATEUSER: d5009410; UPDATETIME: 15:37:05; SAVECOUNT: 4; OriginalSymbolOrigin: (10160,284480); SHTSAVECOUNT: 40; NUMBER DEVICES IN PACKAGE: 1; SHEET NUM: X/X; PIN NUMBERS VISIBLE: False; CONTROL NUM: RD256-SCHEMATIC-0; PIN NAMES ROTATE: True

## Sheet 3.SchDoc
size 420 x 297 mm
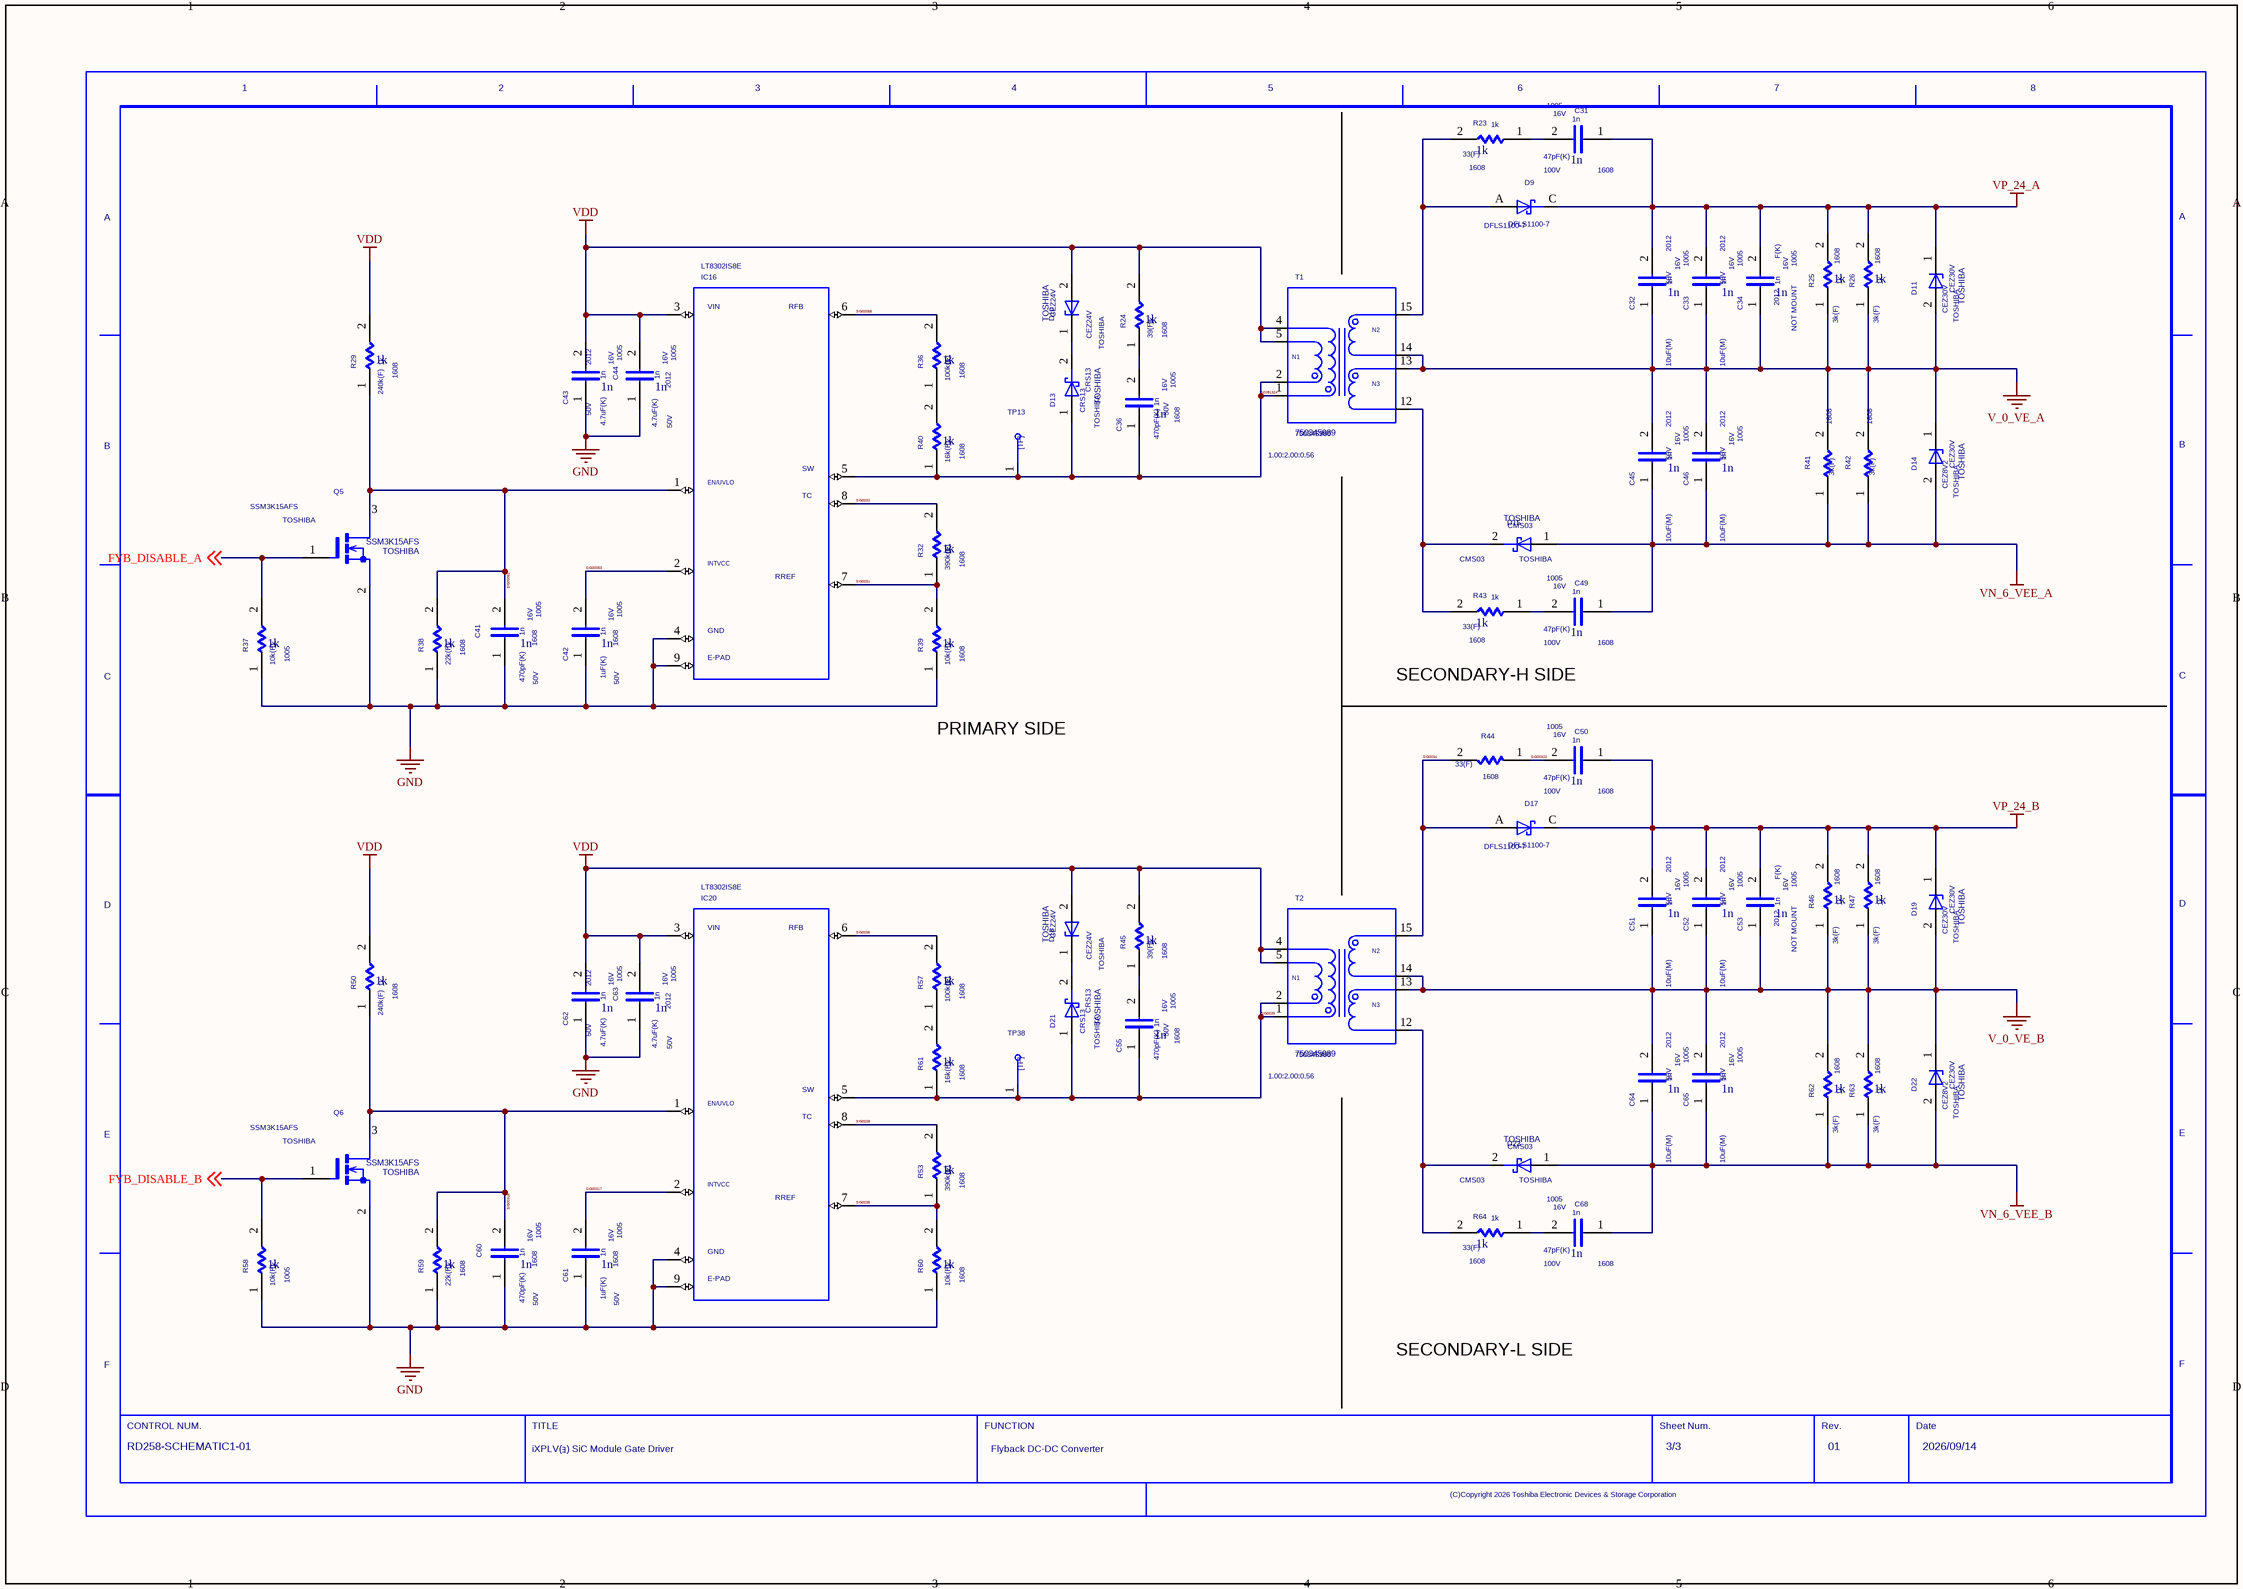
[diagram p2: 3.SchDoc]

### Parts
(Parts that share a designator on the sheet are numbered #1, #2 ... from top to bottom, then left to right.)
C31  1n  VAL1: 47pF(K)  SIZE: 1005  VOLTAGE: 16V  SIZECODESMD: 1608  VAL2: 100V
C32  1n  VAL1: 10uF(M)  SIZE: 1005  VOLTAGE: 16V  SIZECODESMD: 2012  VAL2: 50V
C33  1n  VAL1: 10uF(M)  SIZE: 1005  VOLTAGE: 16V  SIZECODESMD: 2012  VAL2: 50V
C34  1n  VAL1: F(K)  SIZE: 1005  VOLTAGE: 16V  NOTMOUNT: NOT MOUNT  SIZECODESMD: 2012
C36  1n  VAL1: 470pF(K)  SIZE: 1005  VOLTAGE: 16V  SIZECODESMD: 1608  VAL2: 50V
C41  1n  VAL1: 470pF(K)  SIZE: 1005  VOLTAGE: 16V  SIZECODESMD: 1608  VAL2: 50V
C42  1n  VAL1: 1uF(K)  SIZE: 1005  VOLTAGE: 16V  SIZECODESMD: 1608  VAL2: 50V
C43  1n  VAL1: 4.7uF(K)  SIZE: 1005  VOLTAGE: 16V  SIZECODESMD: 2012  VAL2: 50V
C44  1n  VAL1: 4.7uF(K)  SIZE: 1005  VOLTAGE: 16V  SIZECODESMD: 2012  VAL2: 50V
C45  1n  VAL1: 10uF(M)  SIZE: 1005  VOLTAGE: 16V  SIZECODESMD: 2012  VAL2: 50V
C46  1n  VAL1: 10uF(M)  SIZE: 1005  VOLTAGE: 16V  SIZECODESMD: 2012  VAL2: 50V
C49  1n  VAL1: 47pF(K)  SIZE: 1005  VOLTAGE: 16V  SIZECODESMD: 1608  VAL2: 100V
C50  1n  VAL1: 47pF(K)  SIZE: 1005  VOLTAGE: 16V  SIZECODESMD: 1608  VAL2: 100V
C51  1n  VAL1: 10uF(M)  SIZE: 1005  VOLTAGE: 16V  SIZECODESMD: 2012  VAL2: 50V
C52  1n  VAL1: 10uF(M)  SIZE: 1005  VOLTAGE: 16V  SIZECODESMD: 2012  VAL2: 50V
C53  1n  VAL1: F(K)  SIZE: 1005  VOLTAGE: 16V  NOTMOUNT: NOT MOUNT  SIZECODESMD: 2012
C55  1n  VAL1: 470pF(K)  SIZE: 1005  VOLTAGE: 16V  SIZECODESMD: 1608  VAL2: 50V
C60  1n  VAL1: 470pF(K)  SIZE: 1005  VOLTAGE: 16V  SIZECODESMD: 1608  VAL2: 50V
C61  1n  VAL1: 1uF(K)  SIZE: 1005  VOLTAGE: 16V  SIZECODESMD: 1608  VAL2: 50V
C62  1n  VAL1: 4.7uF(K)  SIZE: 1005  VOLTAGE: 16V  SIZECODESMD: 2012  VAL2: 50V
C63  1n  VAL1: 4.7uF(K)  SIZE: 1005  VOLTAGE: 16V  SIZECODESMD: 2012  VAL2: 50V
C64  1n  VAL1: 10uF(M)  SIZE: 1005  VOLTAGE: 16V  SIZECODESMD: 2012  VAL2: 50V
C65  1n  VAL1: 10uF(M)  SIZE: 1005  VOLTAGE: 16V  SIZECODESMD: 2012  VAL2: 50V
C68  1n  VAL1: 47pF(K)  SIZE: 1005  VOLTAGE: 16V  SIZECODESMD: 1608  VAL2: 100V
D9  DFLS1100-7
D10  CEZ24V  VENDOR: TOSHIBA
D11  CEZ30V  VENDOR: TOSHIBA
D13  CRS13  VENDOR: TOSHIBA
D14  CEZ30V  VENDOR: TOSHIBA  VAL3: CEZ8V2
D15  CMS03  VENDOR: TOSHIBA
D17  DFLS1100-7
D18  CEZ24V  VENDOR: TOSHIBA
D19  CEZ30V  VENDOR: TOSHIBA
D21  CRS13  VENDOR: TOSHIBA
D22  CEZ30V  VENDOR: TOSHIBA  VAL3: CEZ8V2
D23  CMS03  VENDOR: TOSHIBA
IC16  LT8302IS8E
IC20  LT8302IS8E
Q5  SSM3K15AFS  VENDOR: TOSHIBA
Q6  SSM3K15AFS  VENDOR: TOSHIBA
R23  1k  VAL1: 33(F)  SIZECODESMD: 1608
R24  1k  VAL1: 39(F)  SIZECODESMD: 1608
R25  1k  VAL1: 3k(F)  SIZECODESMD: 1608
R26  1k  VAL1: 3k(F)  SIZECODESMD: 1608
R29  1k  VAL1: 240k(F)  SIZECODESMD: 1608
R32  1k  VAL1: 390k(F)  SIZECODESMD: 1608
R36  1k  VAL1: 100k(F)  SIZECODESMD: 1608
R37  1k  VAL1: 10k(F)  SIZECODESMD: 1005
R38  1k  VAL1: 22k(F)  SIZECODESMD: 1608
R39  1k  VAL1: 10k(F)  SIZECODESMD: 1608
R40  1k  VAL1: 16k(F)  SIZECODESMD: 1608
R41  VAL1: 3k(F)  SIZECODESMD: 1608  (hidden comment: R)
R42  VAL1: 3k(F)  SIZECODESMD: 1608  (hidden comment: R)
R43  1k  VAL1: 33(F)  SIZECODESMD: 1608
R44  VAL1: 33(F)  SIZECODESMD: 1608  (hidden comment: R)
R45  1k  VAL1: 39(F)  SIZECODESMD: 1608
R46  1k  VAL1: 3k(F)  SIZECODESMD: 1608
R47  1k  VAL1: 3k(F)  SIZECODESMD: 1608
R50  1k  VAL1: 240k(F)  SIZECODESMD: 1608
R53  1k  VAL1: 390k(F)  SIZECODESMD: 1608
R57  1k  VAL1: 100k(F)  SIZECODESMD: 1608
R58  1k  VAL1: 10k(F)  SIZECODESMD: 1005
R59  1k  VAL1: 22k(F)  SIZECODESMD: 1608
R60  1k  VAL1: 10k(F)  SIZECODESMD: 1608
R61  1k  VAL1: 16k(F)  SIZECODESMD: 1608
R62  1k  VAL1: 3k(F)  SIZECODESMD: 1608
R63  1k  VAL1: 3k(F)  SIZECODESMD: 1608
R64  1k  VAL1: 33(F)  SIZECODESMD: 1608
T1  750345989  VAL1: 1.00:2.00:0.56
T2  750345989  VAL1: 1.00:2.00:0.56
TP13  TP  (value not drawn)
TP38  TP  (value not drawn)
U?#3  DATE: 2026/09/14  DRAWINGNUMBER: RD258-SCHEMATIC1-01  TITLE: iXPLV(ｮ) SiC Module Gate Driver  FUNCTION: Flyback DC-DC Converter  SHEETNUMBER: 3/3  REVISION: 01  (hidden comment: WAKU_DEF100)

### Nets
GND: C41.1 C42.1 C43.1 C44.1 C60.1 C61.1 C62.1 C63.1 IC16.4 IC16.9 IC20.4 IC20.9 Q5.2(S) Q6.2(S) R37.1 R38.1 R39.1 R58.1 R59.1 R60.1
V_0_VE_A: C32.1 C33.1 C34.1 C45.2 C46.2 D11.2(A) D14.1(C) R25.1 R26.1 R41.2 R42.2 T1.13 T1.14
V_0_VE_B: C51.1 C52.1 C53.1 C64.2 C65.2 D19.2(A) D22.1(C) R46.1 R47.1 R62.2 R63.2 T2.13 T2.14
VDD: C43.2 C44.2 C62.2 C63.2 D10.2(A) D18.2(A) IC16.3 IC20.3 R24.2 R29.2 R45.2 R50.2 T1.4 T1.5 T2.4 T2.5
VN_6_VEE_A: C45.1 C46.1 C49.1 D14.2(A) D15.1(A) R41.1 R42.1
VN_6_VEE_B: C64.1 C65.1 C68.1 D22.2(A) D23.1(A) R62.1 R63.1
VP_24_A: C31.1 C32.2 C33.2 C34.2 D9.C D11.1(C) R25.2 R26.2
VP_24_B: C50.1 C51.2 C52.2 C53.2 D17.C D19.1(C) R46.2 R47.2
FYB_DISABLE_A: Q5.1(G) R37.2 ; off-sheet FYB_DISABLE_A
FYB_DISABLE_B: Q6.1(G) R58.2 ; off-sheet FYB_DISABLE_B
N2091324: C36.1 D13.1(A) IC16.5 R40.1 T1.1 T1.2 TP13.1
SIG0031: IC16.7 R32.1 R39.2
SIG0032: IC16.8 R32.2
SIG0033: C49.2 R43.1
SIG0034: D17.A R44.2 T2.15
SIG0035: IC20.7 R53.1 R60.2
SIG0036: IC20.6 R57.2
SIG0037: C68.2 R64.1
SIG0038: IC20.8 R53.2
SIG0039: C55.1 D21.1(A) IC20.5 R61.1 T2.1 T2.2 TP38.1
SIG00040: D10.1(C) D13.2(C)
SIG00041: C36.2 R24.1
SIG00042: D9.A R23.2 T1.15
SIG00043: C31.2 R23.1
SIG00050: D15.2(C) R43.2 T1.12
SIG00052: C41.2 IC16.1 Q5.3(D) R29.1 R38.2
SIG00053: C42.2 IC16.2
SIG00055: IC16.6 R36.2
SIG00310: D23.2(C) R64.2 T2.12
SIG00311: C55.2 R45.1
SIG00312: D18.1(C) D21.2(C)
SIG00317: C61.2 IC20.2
SIG00318: C60.2 IC20.1 Q6.3(D) R50.1 R59.2
SIG00320: C50.2 R44.1
NetR36_1: R36.1 R40.2
NetR57_1: R57.1 R61.2

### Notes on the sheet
- SECONDARY-H SIDE
- PRIMARY SIDE
- SECONDARY-L SIDE

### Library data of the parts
C31 C49 C50 C68 = C: TIME: 11:55:01; UPDATEUSER: HP_Z8_KEYSHOT; SAVECOUNT: 2; TC1: 0; PSPICETEMPLATE: C^@REFDES %1 %2 ?TOLERANCE¦C^@REFDES¦ @VALUE ?IC/IC=@IC/ TC=@TC1,@TC2 ?TOLERANCE¦\n.model C^@REFDES CAP C=1 DEV=@TOLERANCE% TC1=@TC1 TC2=@TC2 VC1=@VC1 VC2=@VC2¦; ORIGINALSYMBOLORIGIN: (0,0); INSTANCENAME: INS2090890
C32-C34 C45 C46 C51-C53 C64 C65 = C: TIME: 11:55:01; UPDATEUSER: HP_Z8_KEYSHOT; SAVECOUNT: 2; TC1: 0; PSPICETEMPLATE: C^@REFDES %1 %2 ?TOLERANCE¦C^@REFDES¦ @VALUE ?IC/IC=@IC/ TC=@TC1,@TC2 ?TOLERANCE¦\n.model C^@REFDES CAP C=1 DEV=@TOLERANCE% TC1=@TC1 TC2=@TC2 VC1=@VC1 VC2=@VC2¦; ORIGINALSYMBOLORIGIN: (0,0); INSTANCENAME: INS2091140
C36 C44 C55 C63 = C: TIME: 11:55:01; UPDATEUSER: HP_Z8_KEYSHOT; SAVECOUNT: 2; TC1: 0; PSPICETEMPLATE: C^@REFDES %1 %2 ?TOLERANCE¦C^@REFDES¦ @VALUE ?IC/IC=@IC/ TC=@TC1,@TC2 ?TOLERANCE¦\n.model C^@REFDES CAP C=1 DEV=@TOLERANCE% TC1=@TC1 TC2=@TC2 VC1=@VC1 VC2=@VC2¦; ORIGINALSYMBOLORIGIN: (0,0); INSTANCENAME: INS2091518
C41 C42 C60 C61 = C: TIME: 11:55:01; UPDATEUSER: HP_Z8_KEYSHOT; SAVECOUNT: 2; TC1: 0; PSPICETEMPLATE: C^@REFDES %1 %2 ?TOLERANCE¦C^@REFDES¦ @VALUE ?IC/IC=@IC/ TC=@TC1,@TC2 ?TOLERANCE¦\n.model C^@REFDES CAP C=1 DEV=@TOLERANCE% TC1=@TC1 TC2=@TC2 VC1=@VC1 VC2=@VC2¦; ORIGINALSYMBOLORIGIN: (0,0); INSTANCENAME: INS2092186
C43 C62 = C: TIME: 11:55:01; UPDATEUSER: HP_Z8_KEYSHOT; SAVECOUNT: 2; TC1: 0; PSPICETEMPLATE: C^@REFDES %1 %2 ?TOLERANCE¦C^@REFDES¦ @VALUE ?IC/IC=@IC/ TC=@TC1,@TC2 ?TOLERANCE¦\n.model C^@REFDES CAP C=1 DEV=@TOLERANCE% TC1=@TC1 TC2=@TC2 VC1=@VC1 VC2=@VC2¦; ORIGINALSYMBOLORIGIN: (0,0); INSTANCENAME: INS2092266
D9 D17 = DFLS1100: TIME: 14:49:55; UPDATEUSER: fukuda-y; UPDATETIME: 08:18:42; SAVECOUNT: 6; SAVEAREA0: -4630,-153,17114,13055; PSPICETEMPLATE: X^@REFDES %C %A @MODEL; ORIGINALSYMBOLORIGIN: (0,0); INSTANCENAME: INS2090946
D10 D18 = CEZ24V: TIME: 14:49:55; UPDATEUSER: fukuda-y; UPDATETIME: 08:18:42; SAVECOUNT: 6; SAVEAREA0: -4630,-153,17114,13055; PSPICETEMPLATE: X^@REFDES %A %C @MODEL; ORIGINALSYMBOLORIGIN: (0,0); INSTANCENAME: INS2091294
D11 D14 D19 D22 = CEZ30V: TIME: 14:49:55; UPDATEUSER: fukuda-y; UPDATETIME: 08:18:42; SAVECOUNT: 6; SAVEAREA0: -4630,-153,17114,13055; PSPICETEMPLATE: X^@REFDES %C %A @MODEL; ORIGINALSYMBOLORIGIN: (0,0); INSTANCENAME: INS2091274
D13 D21 = CRS13: TIME: 14:49:55; UPDATEUSER: fukuda-y; UPDATETIME: 08:18:42; SAVECOUNT: 6; SAVEAREA0: -4630,-153,17114,13055; PSPICETEMPLATE: X^@REFDES %A %C @MODEL; ORIGINALSYMBOLORIGIN: (0,0); INSTANCENAME: INS2091426
D15 D23 = CMS03: TIME: 14:49:55; UPDATEUSER: fukuda-y; UPDATETIME: 08:16:22; SAVECOUNT: 9; SAVEAREA0: -4630,-153,17114,13055; PSPICETEMPLATE: X^@REFDES %A %C @MODEL; ORIGINALSYMBOLORIGIN: (0,0); INSTANCENAME: INS2091824
IC16 IC20 = LT8302: TIME: 11:55:00; UPDATEUSER: t5459927; UPDATETIME: 18:09:57; SAVECOUNT: 8; PSPICETEMPLATE: X^@REFDES %EN/UVLO %INTVCC %VIN %GND %SW %RFB %RREF %TC %EXPOSED_PAD @MODEL; OriginalSymbolOrigin: (0,0); INSTANCENAME: INS2091844
Q5 Q6 = SSM3K15AFS: TIME: 11:54:59; UPDATEUSER: HP_Z8_KEYSHOT; UPDATETIME: 11:55:00; SAVECOUNT: 2; ORIGINALSYMBOLORIGIN: (0,0); PSPICETEMPLATE: X^@REFDES %D %G %S @MODEL; INSTANCENAME: INS2091762
R23 R43 R64 = R_Dup1: TIME: 11:54:58; UPDATEUSER: HP_Z8_KEYSHOT; UPDATETIME: 11:54:59; SAVECOUNT: 2; WATT: 0.125; COMP: R; TC1: 0; PSPICETEMPLATE: R^@REFDES %1 %2 ?TOLERANCE¦R^@REFDES¦ @VALUE TC=@TC1,@TC2 ?TOLERANCE¦\n.model R^@REFDES RES R=1 DEV=@TOLERANCE% TC1=@TC1 TC2=@TC2¦; ORIGINALSYMBOLORIGIN: (0,0); VAL2: 100mW; INSTANCENAME: INS2090866
R24 R29 R32 R36-R40 R45 R50 R53 R57-R61 = R_Dup1: TIME: 11:54:58; UPDATEUSER: HP_Z8_KEYSHOT; UPDATETIME: 11:54:59; SAVECOUNT: 2; WATT: 0.125; COMP: R; TC1: 0; PSPICETEMPLATE: R^@REFDES %1 %2 ?TOLERANCE¦R^@REFDES¦ @VALUE TC=@TC1,@TC2 ?TOLERANCE¦\n.model R^@REFDES RES R=1 DEV=@TOLERANCE% TC1=@TC1 TC2=@TC2¦; ORIGINALSYMBOLORIGIN: (0,0); VAL2: 100mW; INSTANCENAME: INS2091678
R25 R26 R46 R47 R62 R63 = R_Dup1: TIME: 11:54:58; UPDATEUSER: HP_Z8_KEYSHOT; UPDATETIME: 11:54:59; SAVECOUNT: 2; WATT: 0.125; COMP: R; TC1: 0; PSPICETEMPLATE: R^@REFDES %1 %2 ?TOLERANCE¦R^@REFDES¦ @VALUE TC=@TC1,@TC2 ?TOLERANCE¦\n.model R^@REFDES RES R=1 DEV=@TOLERANCE% TC1=@TC1 TC2=@TC2¦; ORIGINALSYMBOLORIGIN: (0,0); VAL2: 100mW; INSTANCENAME: INS2091226
R41 R42 R44 = R: VAL2: 100mW; OriginalSymbolOrigin: (5080,5080); SAVECOUNT: 0
T1 T2 = 750345989_2: TIME: 11:55:02; UPDATEUSER: t5459927; UPDATETIME: 19:39:05; SAVECOUNT: 3; PSPICETEMPLATE: X^@REFDES %1 %2 %3 %4 %5 %6 %7 %8 @MODEL; OriginalSymbolOrigin: (0,0); INSTANCENAME: INS2101815
TP13 TP38 = TP: TIME: 16:12:21; UPDATEUSER: fukuda-y; UPDATETIME: 16:18:11; SAVECOUNT: 2; SAVEAREA0: -242,-92,12810,7836; ORIGINALSYMBOLORIGIN: (0,0); INSTANCENAME: INS2091728
U?#3 = WAKU_DEF100: as U?#2 on sheet 2

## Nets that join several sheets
GND: 1 (41 pins), 2 (20 pins), 3 (20 pins)
V_0_VE_A: 2 (CN2.3 CN2.4), 3 (13 pins)
V_0_VE_B: 2 (CN3.3 CN3.4), 3 (13 pins)
VDD: 1 (11 pins), 3 (16 pins)
VN_6_VEE_A: 2 (6 pins), 3 (7 pins)
VN_6_VEE_B: 2 (6 pins), 3 (7 pins)
VP_5_A: 1 (13 pins), 2 (9 pins)
VP_5_B: 1 (13 pins), 2 (8 pins)
VP_24_A: 2 (CN2.1 CN2.2), 3 (8 pins)
VP_24_B: 2 (CN3.1 CN3.2), 3 (8 pins)
A_FLT: 1 (CN1.8 D6.1), 2 (C6.2 Q1.3 R2.1)
A_INA_GATE: 1 (IC26.4), 2 (Q2.1 R11.2)
B_FLT: 1 (CN1.3 D5.1), 2 (C22.2 Q4.3 R16.1 R107.1)
B_INA_GATE: 1 (IC25.4), 2 (Q3.1 R20.2)
FYB_DISABLE_A: 1 (IC27.4), 3 (Q5.1 R37.2)
FYB_DISABLE_B: 1 (IC28.4), 3 (Q6.1 R58.2)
